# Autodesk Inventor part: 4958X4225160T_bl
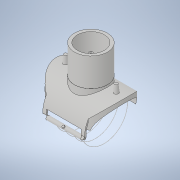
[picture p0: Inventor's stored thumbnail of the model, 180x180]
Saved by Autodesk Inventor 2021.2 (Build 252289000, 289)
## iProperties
Created: 2020-06
Part Number: 4958X4225160T_bl
Material: Generic
Description: Plasson Branch Saddle 225x160
Document SubType Name: Modeling
Designer: KIM
Density: 1 g/cm^3
Appearance: Default
Author: KIM
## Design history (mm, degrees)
derived "4958X4.ipt"
feature "Solid1::4958X4.ipt" dims "ScaleForDerivedMember" = 10
tag "TaggingFeature1"
body "Solid1"
other parameters: "d0" = 338 [user parameter], "d2" = 225 [user parameter], "d3" = 264.6 [user parameter], "d4" = 167 [user parameter], "d7" = 131 [user parameter], "d9" = 137 [user parameter], "d10" = 0.5 [user parameter], "d11" = 1 [user parameter], "d12" = 41.75 [user parameter], "d13" = 16 [user parameter], "d14" = 8 [user parameter], "d16" = 10 deg [user parameter], "d17" = 10 deg [user parameter], "d19" = 0 [user parameter], "d23" = 0 [user parameter], "d26" = 0 [user parameter], "d27" = 202.8 [user parameter], "d28" = 0 [user parameter], "d29" = 169 [user parameter], "d30" = 0 [user parameter], "d31" = 1 [user parameter], "d32" = 1 [user parameter], "d33" = 19.2 [user parameter], "d34" = 9.6 [user parameter], "d35" = 45 deg [user parameter], "d36" = 169 [user parameter], "d37" = 0 [user parameter], "d38" = 5 [user parameter], "d39" = 85 deg [user parameter], "d40" = 41.75 [user parameter], "d41" = 16 [user parameter], "d42" = 122.90909 [user parameter], "d49" = 3 [user parameter], "d50" = 6 [user parameter], "d51" = 5 [user parameter], "d54" = 0 [user parameter], "d57" = 35 deg [user parameter], "d60" = 21.125 [user parameter], "d61" = 1 [user parameter], "d62" = 90 deg [user parameter], "d63" = 2 [user parameter], "d64" = 0 [user parameter], "d65" = 0 [user parameter], "d68" = 42.25 [user parameter], "d70" = 0.57711 [user parameter], "d71" = 10 deg [user parameter], "d73" = 6.93 [user parameter], "d" = 225 [user parameter], "B" = 291 [user parameter], "L" = 338 [user parameter], "LS" = 137 [user parameter], "H1" = 167 [user parameter], "Dt" = 16 [user parameter], "di" = 131 [user parameter], "d72" = 19.8 [user parameter]
